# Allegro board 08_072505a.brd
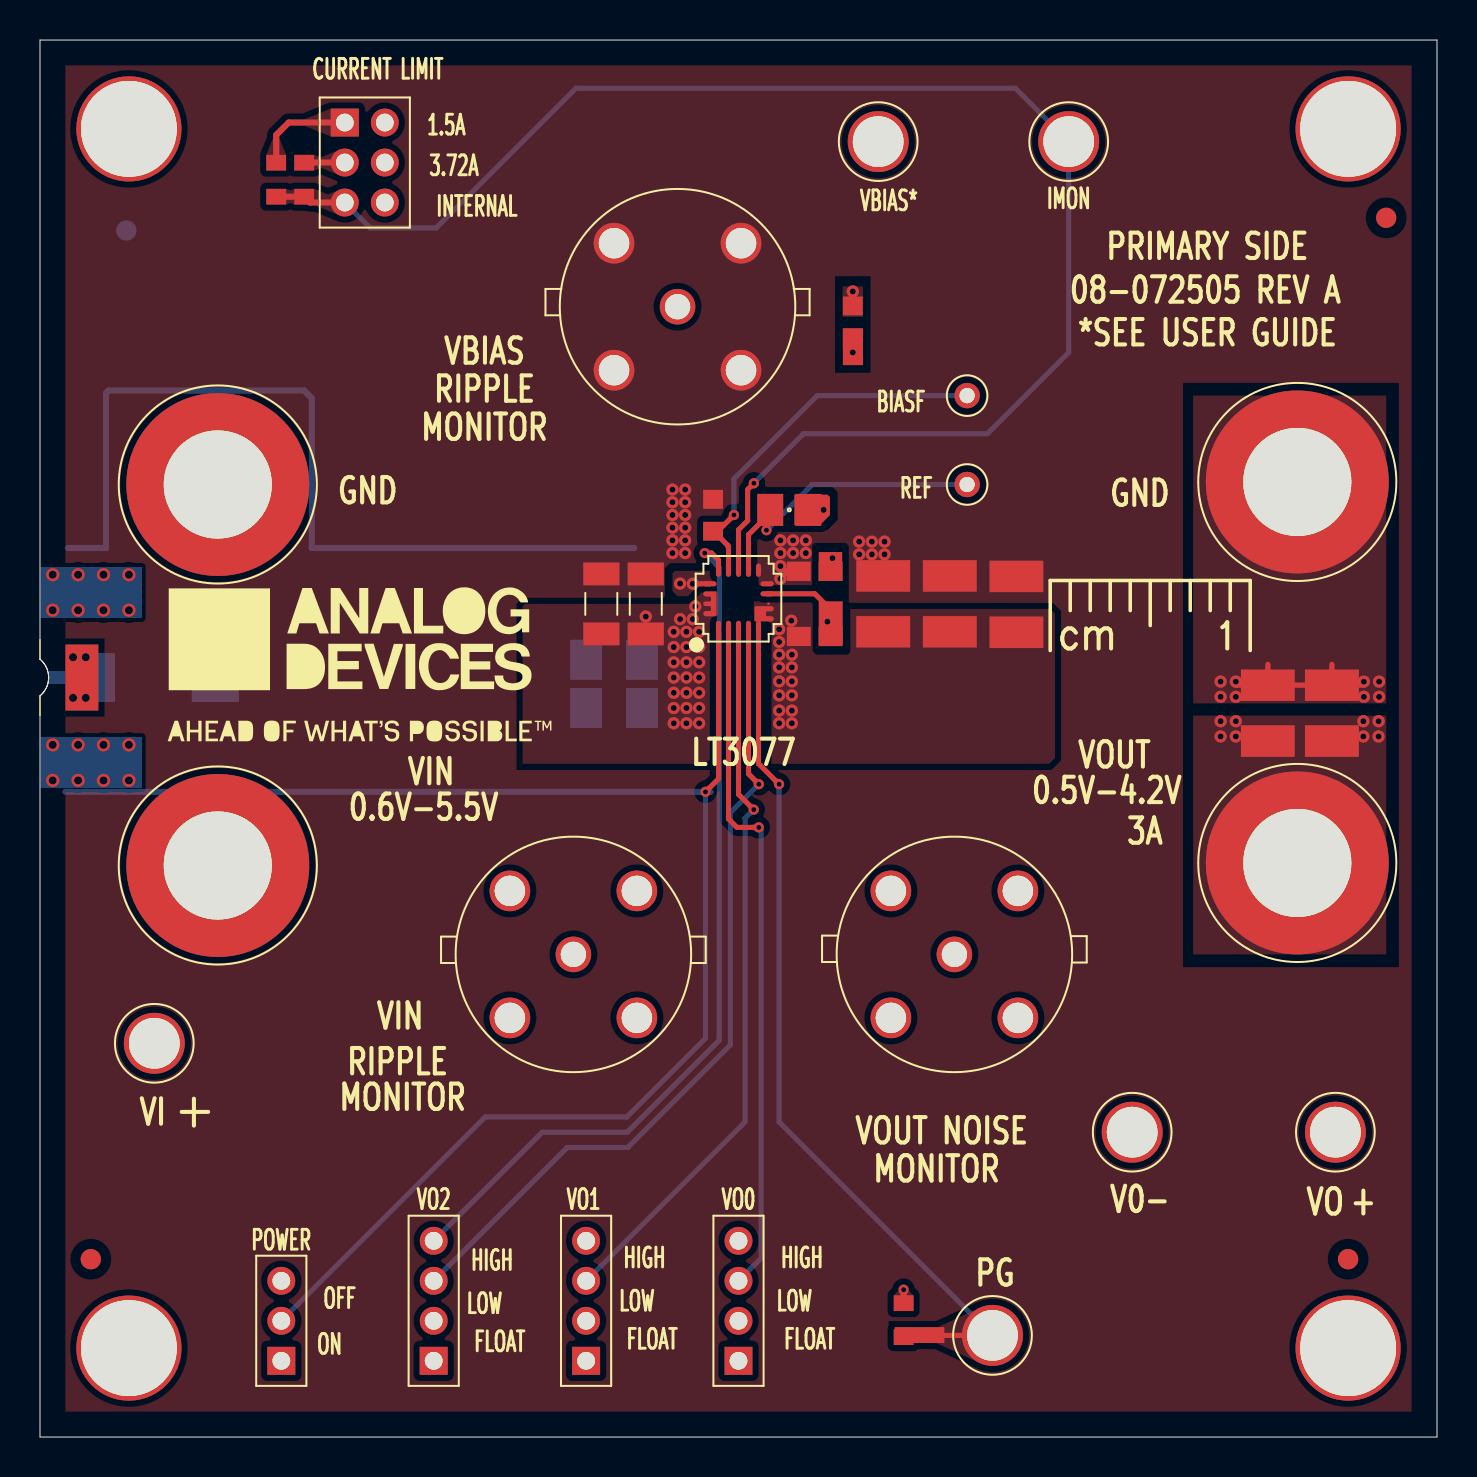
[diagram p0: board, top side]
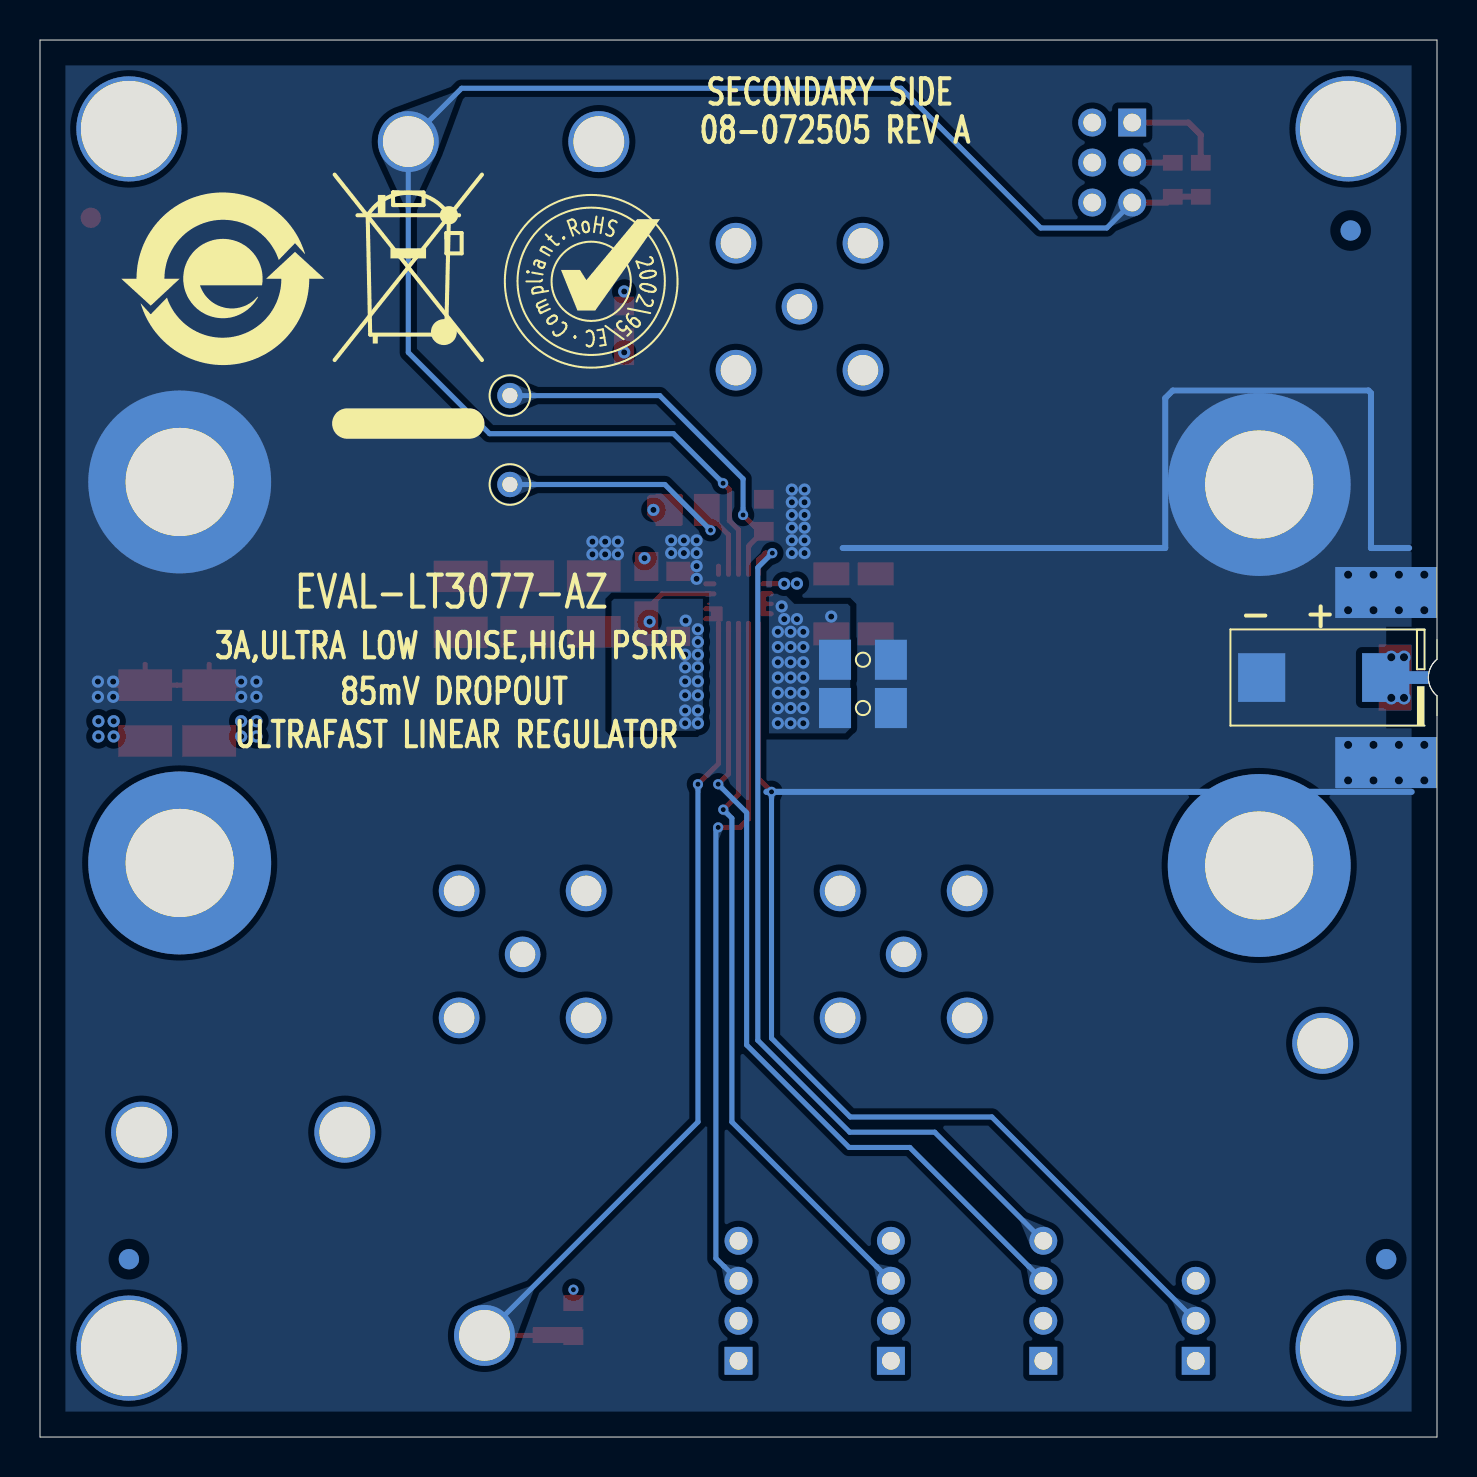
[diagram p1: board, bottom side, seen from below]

Outline 69.85 x 69.85 mm; copper layers: TOP, L2_GND, L3_VCC, BOTTOM. Coordinates in mm from the lower left corner of the outline.
Outline path: 0,69.85 0,38.89 0.07,38.83 0.1,38.8 0.14,38.76 0.19,38.69 0.2,38.67 0.28,38.55 0.31,38.49 0.34,38.42 0.36,38.37 0.38,38.32 0.39,38.29 0.41,38.18 0.42,38.12 0.42,38.1 0.43,38.04 0.43,38 0.43,37.94 0.43,37.91 0.42,37.78 0.41,37.73 0.39,37.66 0.35,37.53 0.34,37.52 0.28,37.39 0.19,37.25 0.15,37.2 0.13,37.18 0.06,37.12 0,37.06 0,0 69.85,0 69.85,69.85 0,69.85

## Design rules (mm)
constraint set DEFAULT: min track width 0.254

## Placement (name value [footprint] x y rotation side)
C1  4.7UF  [C0805H60]  37.47 46.35 0 top
C2  2.2uF  [C0603]  33.66 46.09 270 top
C3  22UF  [C1210H106_SP]  38.73 41.66 90 top
C4  220UF  [C7343-31]  5.67 37.97 0 bottom
C5  TBD1210  [C1210]  42.16 41.66 90 top
C6  TBD0603  [C0603]  40.64 55.75 270 top
C7  TBD1210  [C1210]  45.49 41.66 90 top
C8  TBD1210  [C1210]  48.82 41.63 90 top
C9  TBD1210  [C1210]  61.39 36.2 90 top
C10  TBD1210  [C1210]  64.59 36.2 90 top
C11  TBD1206  [C1206]  30.29 41.66 90 top
C12  TBD1206  [C1206]  28.07 41.66 90 top
CIN1  47UF  [C1206H71]  28.7 38.86 180 bottom
CIN2  47UF  [C1206H71]  28.7 36.45 180 bottom
E1  2501-2-00-80-00-00-07-0  [CNMILLMAX2501]  41.91 64.77 0 top
E2  2501-2-00-80-00-00-07-0  [CNMILLMAX2501]  5.71 19.69 0 top
E3  2501-2-00-80-00-00-07-0  [CNMILLMAX2501]  47.62 5.08 0 top
E4  2501-2-00-80-00-00-07-0  [CNMILLMAX2501]  54.61 15.24 0 top
E5  2501-2-00-80-00-00-07-0  [CNMILLMAX2501]  64.77 15.24 0 top
E6  2501-2-00-80-00-00-07-0  [CNMILLMAX2501]  51.44 64.77 0 top
J1  575-4  [CNBANANAD312LD203]  8.89 28.57 0 top
J2  575-4  [CNBANANAD312LD203]  8.89 47.62 0 top
J3  112404  [CNAMPHENOL112404]  26.67 24.13 0 top
J4  112404  [CNAMPHENOL112404]  31.88 56.52 0 top
J5  112404  [CNAMPHENOL112404]  45.72 24.13 0 top
J6  575-4  [CNBANANAD312LD203]  62.87 28.7 0 top
J7  575-4  [CNBANANAD312LD203]  62.87 47.75 0 top
J8  142-0701-851  [CNSMAL562W375H166]  0 37.97 180 bottom
JP1  62000311121  [CNTHMHDR1X3L236W79H244]  12.07 3.81 90 top
JP2  62000411121  [CNTHMHDR1X4L315W79H250]  19.69 3.81 90 top
JP3  62000411121  [CNTHMHDR1X4L315W79H250]  27.3 3.81 90 top
JP4  62000411121  [CNTHMHDR1X4L315W79H250]  34.92 3.81 90 top
JP5  62000621121  [CNTHMHDR2X3L236W157H248]  15.24 65.72 270 top
NOREF  -  []  4.45 4.45 0 top
NOREF#2  -  []  -50.8 240.03 0 top
NOREF#3  -  []  67.77 36.22 0 top
NOREF#4  -  []  204.75 192.51 0 top
NOREF#5  -  []  0 69.85 0 top
NOREF#6  -  []  0 0 0 top
NOREF#7  -  []  -111.76 -130.81 0 top
NOREF#8  -  []  0 0 0 top
NOREF#9  -  []  67.77 36.22 0 top
NOREF#10  -  []  69.85 0 90 top
NOREF#11  -  []  0 0 0 top
NOREF#12  -  [unnamed#2]  67.31 60.96 0 top
NOREF#13  -  []  -111.76 -130.81 0 top
NOREF#14  -  []  0.43 37.98 0 top
NOREF#15  -  [unnamed#2]  2.54 8.89 0 top
NOREF#16  -  []  301.27 155.91 0 top
NOREF#17  -  []  69.85 0 0 top
NOREF#18  -  []  33.92 186.35 0 top
NOREF#19  -  []  35.41 196.51 0 top
NOREF#20  -  []  37.72 62.99 270 top
NOREF#21  -  []  -60.33 196.51 0 top
NOREF#22  -  []  306.27 180.04 90 top
NOREF#23  -  []  -73.66 195.58 0 top
NOREF#24  -  []  67.77 36.22 0 top
NOREF#25  -  []  -60.96 11.43 0 top
NOREF#26  -  []  66.93 47.98 0 top
NOREF#27  -  []  -111.76 -130.81 0 top
NOREF#28  -  []  -111.76 -130.81 0 top
NOREF#29  -  []  154.94 85.09 0 top
NOREF#30  -  []  1.83 65.41 0 top
NOREF#31  -  []  0 0 0 top
NOREF#32  -  []  0 0 0 top
NOREF#33  -  []  66.12 191.41 0 top
NOREF#34  -  []  16 38.61 0 top
NOREF#35  -  []  218.47 169.11 0 top
NOREF#36  -  []  218.64 181 0 top
NOREF#37  -  []  233.88 183.85 180 top
NOREF#38  -  []  0 69.85 0 top
NOREF#39  -  []  4.45 4.45 0 top
NOREF#40  -  []  0 69.85 270 top
NOREF#41  -  []  -60.18 202.21 0 top
NOREF#42  -  [unnamed#2]  65.41 65.41 0 top
NOREF#43  -  []  283.59 348.62 0 top
NOREF#44  -  []  8.97 196.49 0 top
NOREF#45  -  []  0 0 0 top
NOREF#46  -  [unnamed#2]  65.41 4.45 0 top
NOREF#47  -  []  42.88 66.24 0 top
NOREF#48  -  []  -60.22 175.56 0 top
NOREF#49  -  []  69.85 0 90 top
NOREF#50  -  [unnamed#2]  4.45 65.41 0 top
NOREF#51  -  []  301.34 180.04 0 top
NOREF#52  -  []  178.82 174.9 0 top
NOREF#53  -  [unnamed#2]  4.45 4.45 0 top
NOREF#54  -  []  69.85 69.85 180 top
NOREF#55  -  [unnamed#2]  65.41 8.89 0 top
NOREF#56  -  [unnamed#2]  4.32 60.33 180 bottom
NOREF#57  -  []  42.16 66.8 180 bottom
NOREF#58  -  []  60.71 57.91 180 bottom
NOREF#59  -  [unnamed#2]  65.41 8.89 180 bottom
NOREF#60  -  []  42.29 57.79 180 bottom
NOREF#61  -  [unnamed#2]  2.54 8.89 180 bottom
R1  51K  [R0603]  43.18 5.84 270 top
R2  806  [R0603]  13.21 62.87 90 top
R3  2K  [R0603]  11.81 62.87 90 top
TP1  TESTPAD  [TPC50D30]  46.35 52.07 0 top
TP2  TESTPAD  [TPC50D30]  46.35 47.62 0 top
U1  LT3077ACRZ  [QFN18_3X3H25]  34.92 41.91 0 top

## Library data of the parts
C1 = CAP: Tolerance: 10; User Part Number: UPN; alternate symbols: (); part number: CAP_SM-4.7UF,16V,10,E058535,C0805H60; tolerance: 10
C2 = CAP: User Part Number: UPN; Tolerance: 10; alternate symbols: (C0603L); part number: CAP_SM-2.2UF,10V,10,E015288,C0603; tolerance: 10
C3 = CAP_SP: Tolerance: 10; User Part Number: UPN; alternate symbols: (); part number: CAP_SP_SM-22UF,16V,10,E058533,C1210H106_SP; tolerance: 10
C4 = CAPP: Tolerance: 20; User Part Number: UPN; alternate symbols: (); part number: CAPP_SM-220UF,10V,20,E058399,C7343-31; tolerance: 20
C5 C7-C10 = CAP: User Part Number: UPN; alternate symbols: (C1210L); part number: CAP_SM-TBD1210,TBD1210,TBD1210,E016202,C1210
C6 = CAP: User Part Number: UPN; alternate symbols: (C0603L,C0603L_ALT); part number: CAP_SM-TBD0603,TBD0603,TBD0603,E000382,C0603
C11 C12 = CAP: User Part Number: UPN; alternate symbols: (C1206L); part number: CAP_SM-TBD1206,TBD1206,TBD1206,E000384,C1206
CIN1 CIN2 = CAP: Tolerance: 10; User Part Number: UPN; alternate symbols: (C1206H71); part number: CAP_SM-47UF,10V,10,E044853,C1206H71; tolerance: 10
E1-E6 = CNTP1P: User Part Number: UPN; Tolerance: N/A; alternate symbols: (); part number: CNTP1P_TH-2501-2-00-80-00-00-07-0,E031108,CNMILLMAX2501; tolerance: N/A
J1 J2 J6 J7 = CNTP1P: Tolerance: N/A; User Part Number: UPN; alternate symbols: (); part number: CNTP1P_TH-575-4,E012555,CNBANANAD312LD203; tolerance: N/A
J3-J5 = CNBNC5P: Tolerance: N/A; User Part Number: UPN; alternate symbols: (); part number: CNBNC5P_TH-112404,E020078,CNAMPHENOL112404; tolerance: N/A
J8 = CNBNC5P: Tolerance: N/A; User Part Number: UPN; alternate symbols: (CNSMAL562W375H166_HS); part number: CNBNC5P_SM-142-0701-851,E014551,CNSMAL562W375H166; tolerance: N/A
JP1 = CN3P: User Part Number: UPN; Tolerance: N/A; alternate symbols: (); part number: CN3P_TH-62000311121,E033291,CNTHMHDR1X3L236W79H244; tolerance: N/A
JP2-JP4 = CN4P: Tolerance: N/A; User Part Number: UPN; alternate symbols: (); part number: CN4P_TH-62000411121,E034910,CNTHMHDR1X4L315W79H250; tolerance: N/A
JP5 = CN6P: User Part Number: UPN; Tolerance: N/A; alternate symbols: (); part number: CN6P_SM-62000621121,E035206,CNTHMHDR2X3L236W157H248; tolerance: N/A
R1 = RES: User Part Number: UPN; Tolerance: 5; alternate symbols: (R0603L); part number: RES_SM-51K,E059009,1/10W,5,R0603; tolerance: 5
R2 = RES: User Part Number: UPN; Tolerance: 1; alternate symbols: (R0603L); part number: RES_SM-806,E003670,1/10W,1,R0603; tolerance: 1
R3 = RES: User Part Number: UPN; Tolerance: 1; alternate symbols: (R0603L); part number: RES_SM-2K,E016458,1/10W,1,R0603; tolerance: 1
TP1 TP2 = NCTESTPAD: Tolerance: N/A; User Part Number: UPN; alternate symbols: (); part number: NCTESTPAD_TH-TESTPAD,E007450,TPC50D30; tolerance: N/A
U1 = ADLT3077: User Part Number: UPN; Tolerance: N/A; alternate symbols: (); part number: ADLT3077_SM-LT3077ACRZ,E058324,QFN18_3X3H25; tolerance: N/A

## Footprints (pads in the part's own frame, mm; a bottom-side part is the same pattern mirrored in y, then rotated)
C0603
  rect 0.94x0.991 smd: 1(-0.8,0) 2(0.8,0)
C0805H60
  rect 1.295x1.6 smd: 1(-0.953,0) 2(0.953,0)
C1206
  rect 1.143x1.803 smd: 1(-1.5,0) 2(1.5,0)
C1206H71
  rect 1.6x2.007 smd: 1(-1.397,0) 2(1.397,0)
C1210
  rect 1.575x2.692 smd: 1(-1.397,0) 2(1.397,0)
C1210H106_SP
  rect 0.965x1.194 smd: 1(-1.628,-0.797) 2(1.628,-0.797) 3(1.628,0.797) 4(-1.628,0.797)
C7343-31
  rect 2.362x2.438 smd: N(3.1,0) P(-3.1,0)
CNAMPHENOL112404
  round 1.778 hole 1.27: 1(0,0)
  round 2.032 hole 1.524: 2(-3.175,3.175) 3(3.175,3.175) 4(3.175,-3.175) 5(-3.175,-3.175)
CNBANANAD312LD203
  round 9.144 hole 5.41: 1(0,0)
CNMILLMAX2501
  round 3.048 hole 2.54: 1(0,0)
CNSMAL562W375H166
  rect 1.727x0.635 smd: 1(-1.295,0)
  rect 5.08x2.54 smd: 2(-2.54,4.255) 3(-2.54,4.255) 4(-2.54,-4.255) 5(-2.54,-4.255)
CNTHMHDR1X3L236W79H244
  rect 1.397x1.397 hole 0.889: 1(0,0)
  round 1.397 hole 0.889: 2(2,0) 3(4,0)
CNTHMHDR1X4L315W79H250
  rect 1.397x1.397 hole 0.889: 1(0,0)
  round 1.397 hole 0.889: 2(2,0) 3(4,0) 4(6,0)
CNTHMHDR2X3L236W157H248
  rect 1.397x1.397 hole 0.889: 1(0,0)
  round 1.397 hole 0.889: 2(0,2) 3(2,0) 4(2,2) 5(4,0) 6(4,2)
QFN18_3X3H25
  oval 0.254x0.66 smd: 1(-1,-1.43) 2(-0.5,-1.43) 3(0,-1.43) 4(0.5,-1.43) 5(1,-1.43) 10(1,1.43) 11(0.5,1.43) 12(0,1.43) 13(-0.5,1.43) 14(-1,1.43)
  custom 0.191x0.191 smd: 6(1.278,-0.75)
  round 0.127 smd: 7(1.5,-0.25) 17(-1.5,0.25) 18(-1.5,-0.75)
  oval 0.66x0.254 smd: 8(1.43,0.25) 9(1.43,0.75) 15(-1.43,0.75)
  custom 0.165x0.165 smd: 16(-1.43,-0.25)
R0603
  rect 0.787x0.991 smd: 1(-0.85,0) 2(0.85,0)
TPC50D30
  round 1.27 hole 0.762: 1(0,0)
unnamed#2
  round 1.016 smd: (0,0)

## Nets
1: J3.2 J3.3 J3.4 J3.5(SH4) U1.15
2: C1.2(N2) C3.2 E4.1(N1) J5.2 J5.3 J5.4 J5.5(SH4)
GROUND: C2.1 C3.3 C4.N(N2) C5.2(N2) C6.2(N2) C7.2(N2) C8.2(N2) C9.2(N2) C10.2(N2) C11.2(N2) C12.2(N2) CIN1.2(N2) CIN2.2(N2) J2.1(N1) J4.2 J4.3 J4.4 J4.5(SH4) J7.1(N1) J8.2 J8.3 J8.4 J8.5(SH4) JP1.3(N3) JP2.2 JP3.2 JP4.2 JP5.2 JP5.4 JP5.6(N6) U1.9 U1.10
UNNAMED_2_ADLT3077_I96_EN: JP1.2 U1.1
UNNAMED_2_ADLT3077_I96_IN1: C4.P C11.1 C12.1 CIN1.1 CIN2.1 E2.1(N1) J1.1(N1) J3.1 J8.1 U1.16 U1.17 U1.18
UNNAMED_2_ADLT3077_I96_OUT1: C3.4(N4) C5.1 C7.1 C8.1 C9.1 C10.1 J6.1(N1) U1.6 U1.7
UNNAMED_2_ADLT3077_I96_SENSE: C3.1 E5.1(N1) J5.1 U1.8
UNNAMED_2_CAP_I1_N2: C2.2(N2) TP1.1(N1) U1.13
UNNAMED_2_CAP_I82_N1: C1.1 TP2.1(N1) U1.11
UNNAMED_2_CN6P_I64_N1: JP5.1 R3.2(N2)
UNNAMED_2_CN6P_I64_N3: JP5.3 R2.2(N2)
UNNAMED_2_CN6P_I64_N5: E6.1(N1) JP5.5 R2.1 R3.1 U1.12
UNNAMED_2_CNTP1P_I50_N1: E3.1(N1) R1.2(N2) U1.5
VBIAS: C6.1 E1.1(N1) J4.1 JP1.1 JP2.4(N4) JP3.4(N4) JP4.4(N4) R1.1 U1.14
VO0: JP4.3 U1.2
VO1: JP3.3 U1.3
VO2: JP2.3 U1.4(VO2)

Pads without a net: JP2 1; JP3 1; JP4 1

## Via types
v1: diameter 0.61, hole 0.305, TOP to BOTTOM, 89 vias
v2: diameter 0.508, hole 0.254, TOP to BOTTOM, 10 vias
v3: diameter 0.66, hole 0.406, TOP to BOTTOM, 20 vias

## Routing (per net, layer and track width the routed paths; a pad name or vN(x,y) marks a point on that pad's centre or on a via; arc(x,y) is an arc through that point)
1: length 0.9
  TOP w0.254: U1.15 v1(32.64,42.66)
  vias: v1(32,42.67)
2:
  vias: v1(39.18,46.35) v1(39.62,43.94)
GROUND: length 10
  TOP w0.254: 37.4,43.28 v1(37.02,42.91) ; 37.4,43.28 37.28,43.28 v1(37.02,43.54) ; 37.4,43.28 C3.3 ; C10.2 64.59,38.63 ; C10.2 62.99,37.59 ; C10.2 66.19,37.59 ; C9.2 61.39,38.63 ; C9.2 59.79,37.59 ; C9.2 62.99,37.59
  vias: v1(31.62,47.37) v1(31.62,46.74) v1(31.62,46.1) v1(31.62,45.47) v1(31.62,44.83) v1(31.62,44.2) v1(32.26,47.37) v1(32.26,46.74) v1(32.26,46.1) v1(32.26,45.47) v1(32.26,44.83) v1(32.26,44.2) v1(37.02,44.83) v1(37.02,44.2) v1(37.66,44.83) v1(37.66,44.2) v1(38.29,44.83) v1(38.29,44.2) v1(40.64,54.23) v1(40.96,44.77) v1(40.96,44.13) v1(41.59,44.77) v1(41.59,44.13) v1(42.23,44.77) v1(42.23,44.13) v1(59.03,37.77) v1(59.03,37.01) v1(59.79,37.77) v1(59.79,37.01) v1(66.19,37.77) v1(66.19,37.01) v1(66.95,37.77) v1(66.95,37.01) v3(0.64,43.12) v3(0.64,41.34) v3(0.64,34.61) v3(0.64,32.83) v3(1.91,43.12) v3(1.91,41.34) v3(1.91,34.61) v3(1.91,32.83) v3(3.18,43.12) v3(3.18,41.34) v3(3.18,34.61) v3(3.18,32.83) v3(4.45,43.12) v3(4.45,41.34) v3(4.45,34.61) v3(4.45,32.83)
UNNAMED_2_ADLT3077_I96_EN: length 47.9
  TOP w0.254: v2(33.27,32.26) 33.93,32.91 U1.1
  BOTTOM w0.254: v2(33.27,32.26) 33.27,19.94 29.34,16 22.26,16 JP1.2
UNNAMED_2_ADLT3077_I96_IN1: length 42.5
  L2_GND w0.508: v1(30.29,41.02) 29.15,39.88 29.15,32.07 26.67,29.59 J3.1
  L3_VCC w0.508: J3.1 19.3,24.13 14.86,19.69 E2.1
  BOTTOM w0.254: J8.1 C4.P
  vias: v1(31.69,40.26) v1(31.69,39.5) v1(31.69,38.73) v1(31.69,37.97) v1(31.69,37.21) v1(31.69,36.45) v1(31.69,35.69) v1(32,40.89) v1(32.32,40.26) v1(32.32,39.5) v1(32.32,38.73) v1(32.32,37.97) v1(32.32,37.21) v1(32.32,36.45) v1(32.32,35.69) v1(32.64,40.89) v1(32.77,41.53) v1(32.96,40.26) v1(32.96,39.5) v1(32.96,38.73) v1(32.96,37.97) v1(32.96,37.21) v1(32.96,36.45) v1(32.96,35.69) v3(1.65,38.99) v3(1.65,36.96) v3(2.29,38.99) v3(2.29,36.96)
UNNAMED_2_ADLT3077_I96_OUT1:
  vias: v1(36.96,40.39) v1(36.96,39.75) v1(36.96,39.12) v1(36.96,38.48) v1(36.96,37.78) v1(36.96,37.08) v1(36.96,36.32) v1(36.96,35.69) v1(37.57,40.82) v1(37.59,39.12) v1(37.59,38.48) v1(37.59,37.78) v1(37.59,37.08) v1(37.59,36.32) v1(37.59,35.69) v1(59.03,35.79) v1(59.03,35.03) v1(59.79,35.79) v1(59.79,35.03) v1(66.17,35.79) v1(66.17,35.03) v1(66.93,35.79) v1(66.93,35.03)
UNNAMED_2_ADLT3077_I96_SENSE: length 45.2
  TOP w0.254: 39.34,41.55 38.74,42.16 U1.8
  L2_GND w0.508: v1(39.37,40.77) 45.72,34.42 J5.1
  L3_VCC w0.508: J5.1 55.88,24.13 E5.1
UNNAMED_2_CAP_I1_N2: length 18.8
  TOP w0.254: v2(34.7,46.1) 33.88,45.29 33.68,45.29 ; U1.13 34.42,44.52 34.38,44.56 34.38,44.58 33.68,45.29 ; 33.68,45.29 C2.2
  BOTTOM w0.254: TP1.1 38.86,52.07 34.7,47.9 v2(34.7,46.1)
UNNAMED_2_CAP_I82_N1: length 15.1
  TOP w0.254: 36.32,46.01 35.43,45.12 U1.11 ; 36.32,46.01 v2(36.32,45.34) ; 36.32,46.01 36.51,46.2 C1.1
  BOTTOM w0.254: v2(36.32,45.34) 38.61,47.62 TP2.1
UNNAMED_2_CN6P_I64_N1: length 5.1
  TOP w0.305: JP5.1 12.43,65.72 11.81,65.1 R3.2
UNNAMED_2_CN6P_I64_N3: length 2
  TOP w0.305: R2.2 13.34,63.72 JP5.3
UNNAMED_2_CN6P_I64_N5: length 77.9
  TOP w0.254: U1.12 34.92,45.36 35.38,45.82 35.38,47.37 v2(35.7,47.69)
  TOP w0.305: JP5.5 13.5,61.72 R2.1 R3.1
  BOTTOM w0.254: v2(35.7,47.69) 38.17,50.16 47.37,50.16 51.44,54.23 E6.1 48.77,67.44 26.8,67.44 19.81,60.45 16.51,60.45 JP5.5
UNNAMED_2_CNTP1P_I50_N1: length 44.7
  TOP w0.254: U1.5 35.92,33.67 v2(36.95,32.64) ; R1.2 43.27,5.08 E3.1
  BOTTOM w0.254: v2(36.95,32.64) 36.95,15.75 E3.1
VBIAS: length 109.7
  TOP w0.254: v2(33.23,44.2) 33.58,44.2 33.93,43.85 U1.14
  TOP w0.305: R1.1 v2(43.18,7.37)
  L2_GND w0.508: E1.1 41.91,58.55 v1(40.64,57.28) 39.88,56.52 J4.1 31.88,50.16 33.23,48.81 v2(33.23,44.2)
  L3_VCC w0.305: v2(43.18,7.37) 37.37,7.37 JP4.4 JP3.4 JP2.4 18.63,9.81 18.6,9.78 18.03,9.78 JP1.1
  BOTTOM w0.254: v2(33.23,44.2) 33.96,43.47 33.96,19.83 29.37,15.24 25.12,15.24 JP2.4
VO0: length 34.5
  TOP w0.254: U1.2 34.42,30.9 34.85,30.48 v2(35.94,30.48)
  BOTTOM w0.254: v2(35.94,30.48) 36.06,30.37 36.06,8.93 35.66,8.54 35.65,8.54 JP4.3
VO1: length 36.5
  TOP w0.254: v2(35.69,31.37) 34.92,32.13 U1.3
  BOTTOM w0.254: v2(35.69,31.37) 35.26,30.94 35.26,15.75 28.04,8.54 28.03,8.54 JP3.3
VO2: length 41.4
  TOP w0.254: U1.4 35.43,33.15 v2(35.94,32.64)
  BOTTOM w0.254: JP2.3 20.41,8.54 20.42,8.54 26.36,14.48 29.39,14.48 34.52,19.6 34.52,31.22 v2(35.94,32.64)

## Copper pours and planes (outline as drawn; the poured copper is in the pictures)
1 on TOP: 33.78,42.55 32.89,42.55 32.39,42.04 31.88,42.04 31.62,42.29 31.62,43.18 31.75,43.31 33.66,43.31 33.78,43.18
1 on L2_GND: 21.69,27.71 21.69,19.15 31.65,19.15 31.75,19.24 31.75,34.8 31.5,35.06 31.5,40.54 31.47,40.56 32.56,41.66 32.77,41.66 32.89,41.78 32.89,42.93 29.46,42.93 27.56,41.02 27.56,33.58
2 on TOP (solid shape): 40.11,42.8 38.94,42.8 38.94,44.25 40.11,44.25
2 on TOP (solid shape): 39.5,46.99 39.5,46.1 38.99,45.59 37.72,45.59 37.72,47.12 39.37,47.12
2 on L2_GND: 38.73,46.86 38.73,46.1 39.37,45.47 39.37,37.85 40.89,36.32 40.89,19.43 41.02,19.3 48.9,19.3 54.1,14.1 55.75,15.75 50.55,20.96 50.55,32.64 40.26,42.93 40.26,45.97 39.37,46.86
GROUND on TOP (solid shape): 41.15,53.59 40.14,53.59 40.14,55.42 41.15,55.42
GROUND on TOP: 1.27,68.58 68.58,68.58 68.58,1.27 1.27,1.27 ; 6 cut-outs
GROUND on TOP: 57.66,52.07 57.66,36.68 67.31,36.68 67.31,52.07
GROUND on BOTTOM: 1.27,68.58 68.58,68.58 68.58,1.27 1.27,1.27 ; 1 cut-out
GROUND on L2_GND: 1.27,68.58 1.27,1.27 68.58,1.27 68.58,68.58 ; 2 cut-outs
GROUND on L3_VCC: 1.27,68.58 68.58,68.58 68.58,1.27 1.27,1.27
UNNAMED_2_ADLT3077_I96_IN1 on TOP (solid shape): 2.92,36.32 1.27,36.32 1.27,39.62 2.92,39.62
UNNAMED_2_ADLT3077_I96_IN1 on TOP: 33.78,42.29 33.15,42.29 32.51,41.66 24.26,41.66 24.13,41.53 24.13,33.66 33.27,33.66 33.53,33.91 33.53,40.77 33.91,41.15 33.91,42.16
UNNAMED_2_ADLT3077_I96_IN1 on BOTTOM: 32.64,42.16 33.27,42.16 33.4,42.04 33.4,35.18 29.59,35.18 29.34,35.43 29.34,41.53 29.46,41.66 32.13,41.66
UNNAMED_2_ADLT3077_I96_IN1 on L3_VCC: 1.27,44.32 29.97,44.32 30.1,44.2 30.1,42.55 33.27,42.55 33.53,42.29 33.53,33.15 33.4,33.02 13.84,33.02 13.46,32.64 13.46,24.26 13.21,24 3.56,24 3.43,24.13 3.43,32.89 3.05,33.27 1.27,33.27
UNNAMED_2_ADLT3077_I96_OUT1 on TOP: 57.66,36.07 57.66,24.13 67.31,24.13 67.31,36.07
UNNAMED_2_ADLT3077_I96_OUT1 on TOP: 35.69,41.78 38.63,41.78 38.63,39.29 38.81,39.12 40.39,39.12 40.51,39.24 40.51,41.4 50.52,41.4 50.75,41.17 50.75,33.96 50.44,33.66 36.58,33.66 36.58,40.64 36.32,40.89 35.81,40.89 35.69,41.02
UNNAMED_2_ADLT3077_I96_OUT1 on BOTTOM: 36.7,41.91 36.7,35.69 37.08,35.31 41.15,35.31 41.27,35.43 41.27,41.78 41.15,41.91
UNNAMED_2_ADLT3077_I96_OUT1 on L3_VCC: 39.19,43.05 36.65,40.51 36.65,33.58 37.08,33.15 58.04,33.15 58.29,32.89 58.29,24.26 58.42,24.13 67.18,24.13 67.69,24.64 67.69,43.05
UNNAMED_2_ADLT3077_I96_SENSE on TOP (solid shape): 40.13,39.62 38.94,39.62 38.94,41.78 40.13,41.78
UNNAMED_2_CNTP1P_I50_N1 on TOP (solid shape): 45.21,4.7 42.74,4.7 42.74,5.49 45.21,5.49
VBIAS on TOP: 40.13,57.53 40.13,56.01 41.15,56.01 41.15,57.53

Small or netless copper shapes (teardrops, artwork), in the pictures only: 20 on TOP, 22 on BOTTOM, 5 on L2_GND, 12 on L3_VCC

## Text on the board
Ref Des/Silkscreen Bottom: ULTRAFAST LINEAR REGULATOR | 85mV DROPOUT | 3A,ULTRA LOW NOISE,HIGH PSRR | EVAL-LT3077-AZ
User.Comments: SEE NOTE 6 AT 4 PLACES | SEE DETAIL B | AT 6 PLACES | SEE DETAIL A | AT 4 PLACES | 5.    BOARDS TO BE SHIPPED SINGULATED AFTER ASSEMBLY PROCESS. | SMOOTHEN EDGES AND FREE FROM BURRS AFTER DEPANELIZATION PROCESS. | 7.    INSTALL SHUNT CONNECTOR MFG(60800213421) TO THE FOLLOWING HEADER CONNECTOR | JP1 PIN(1&2), JP2 PIN(1&2), JP3 PIN(1&2), JP4 PIN(3&4) AND JP5 PIN(3&4)
Ref Des/Silkscreen Top: POWER | ON | OFF | CURRENT LIMIT | VO2 | 1.5A | 3.72A | INTERNAL | LOW | HIGH | FLOAT | VO1 | VO0 | VBIAS* | BIASF | REF | IMON | VI | GND | RIPPLE | VIN | MONITOR | 0.6V-5.5V | VBIAS | LT3077 | VOUT NOISE | PG | 0.5V-4.2V | VOUT | V0- | 3A | *SEE USER GUIDE | VO
DIMENSION: " " | (REF) | DIA MAX
PAGE_OUTLINE: BOARD Z
User.15: .0035" | .0028" | .0014" | PREPEG | CORE
User.23: L2 GND | 08-      -07
User.24: L3 VCC | 08-      -08
User.45: FIGURE | SIZE | 10.0 | 12.0 | 16.0 | 30.0 | 35.0 | 50.0 | 60.0 | 100.0 | 213.0 | 189.0 | DRILL CHART: TOP to BOTTOM | FINISHED HOLES IN MILS | PLATED | NON-PLATED | QTY | 10 | 89 | 20 | 2 | 21 | 3 | 12 | 6 | 4 | TOLERANCE/NOTES | A
